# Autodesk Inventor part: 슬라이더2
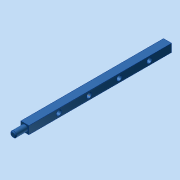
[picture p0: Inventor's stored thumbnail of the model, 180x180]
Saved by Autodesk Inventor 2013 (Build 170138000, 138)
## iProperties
Company: 한국ATC센터
Created: 2015-04
Part Number: 슬라이더2
Document SubType Name: Modeling
Designer: KYOUNG IL JANG
Density: 7.85 g/cm^3
Material: 강철
Mass: 69.0062 g
Surface Area: 52.3143 cm^2
Volume: 8.7906 cm^3
Author: KYOUNG IL JANG
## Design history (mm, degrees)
sketch "스케치3"
  geometry: L1 (4, 142)-(-4, 142); L2 (-4, 142)-(-4, 0); L3 (-4, 0)-(4, 0); L4 (4, 0)-(4, 142); 3 further points
  constraints: 8 end point, 2 coincident, 2 parallel, 1 horizontal, 1 midpoint, 1 perpendicular
  dimensions: "d5" = 8 distance of L1.start L1.end; "d6" = 142 distance of L1.end L2.end
extrude "돌출3" new body sketch "스케치3" stored distance "d7" = 8; taper "d8" = 0 deg
sketch "스케치4"
  geometry: L1 (8, 0)-(0, 0) reference; 3 further points
  constraints: 1 midpoint, 1 vertical alignment
  dimensions: "d9" = 30 distance of point (4, 30) point (4, 0)
hole "구멍1" sketch "스케치4" at (4, 30) diameter "d10" = 5; stored, may be unused: countersink angle "d14" = 90 deg, drill point angle "d16" = 118 deg; dims "d11" = 6, "d12" = 4, "d13" = 2, "d15" = 8
sketch "스케치5"
  geometry: C1 r 3 at (4, -4); 1 further point
  constraints: 1 centre point, 1 coincident
  dimensions: "d20" = 6 diameter of C1
extrude "돌출4" join sketch "스케치5" distance "d21" = 12; taper "d22" = 0 deg
chamfer "모따기1" distance "d23" = 1; stored, may be unused: second distance "d24" = 2, angle "d25" = 45 deg
node "작업 평면2"
  node "작업축1"
node "솔리드1"
pattern_linear "직사각형 패턴1" dims "d19" = 30
node "솔리드2"
other parameters: "d26" = 0
